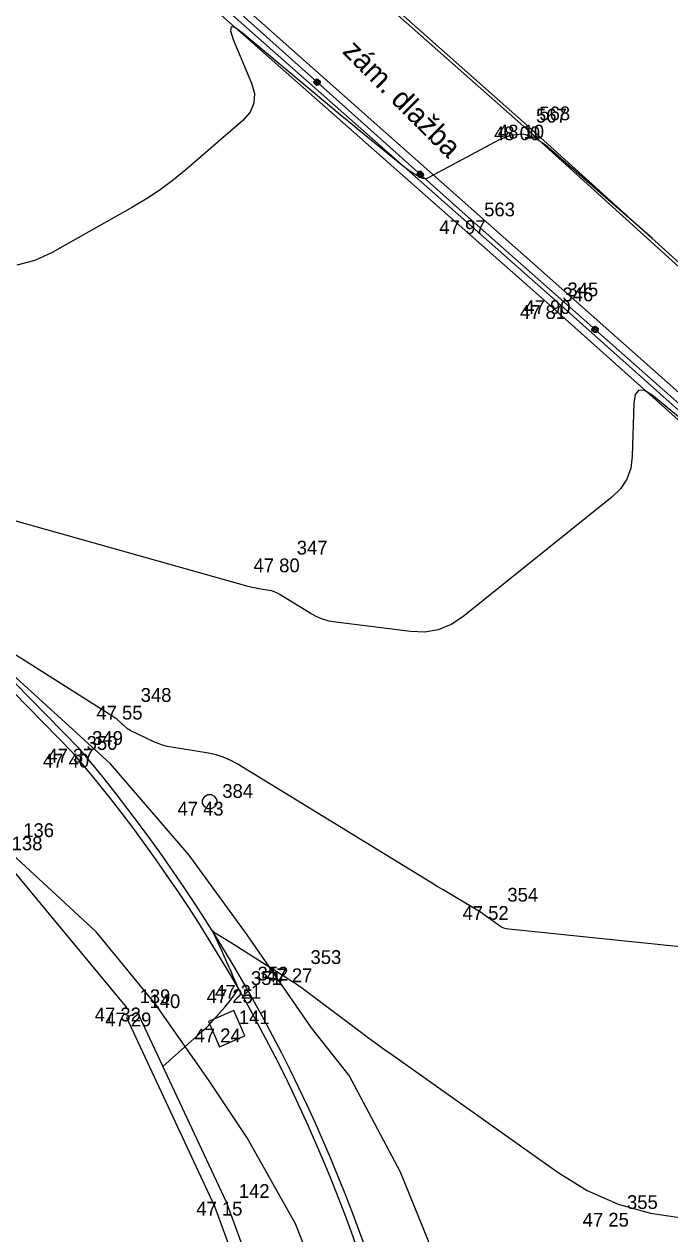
# Model space of a CAD drawing. Extents: x -702257 to -701487, y -1009871 to -1008841.
# Drawn here: x -701672.48 to -701660.77, y -1009023.63 to -1009001.71 of the extents above; entities that cross this region are included whole.
import ezdxf

# ---------------------------------------------------------------- set-up
doc = ezdxf.new("R2010")
doc.units = 0
for name, color, linetype in [('Ex_Major Contours', 7, 'Continuous'), ('Ex_Minor Contours', 7, 'Continuous'), ('Z_body', 7, 'Continuous'), ('Z_body_cisla', 7, 'Continuous'), ('Z_body_vysky_redukovane', 7, 'Continuous'), ('Z_katastr_hranice', 7, 'Continuous'), ('Z_komunikace', 7, 'Continuous'), ('Z_obruba', 7, 'Continuous'), ('Z_ploty', 7, 'Continuous'), ('Z_popisy', 7, 'Continuous'), ('Z_site_nerozlisene_znaky', 7, 'Continuous'), ('Z_site_vodovod_znaky', 7, 'Continuous'), ('Z_vstupy', 7, 'Continuous'), ('Z_zabradli', 7, 'Continuous'), ('Z_zabradli_znaky', 7, 'Continuous')]:
    doc.layers.add(name, color=color, linetype=linetype)

# ---------------------------------------------------------------- blocks, each defined once
blk = doc.blocks.new('POINT_DISPLAY')
blk.add_line((0, 0), (0, 0))
blk = doc.blocks.new('Z614')
for p, q in [((-0.13, 0.03), (-0.1, 0.08)), ((-0.13, -0.03), (-0.13, 0.03)), ((-0.1, 0.08), (-0.08, 0.1)), ((-0.08, 0.1), (-0.03, 0.13)), ((-0.03, 0.13), (0.03, 0.13)), ((0.03, 0.13), (0.08, 0.1)), ((0.08, 0.1), (0.1, 0.08)), ((0.1, 0.08), (0.13, 0.03)), ((0.13, 0.03), (0.13, -0.03)), ((-0.1, -0.08), (-0.13, -0.03)), ((-0.08, -0.1), (-0.1, -0.08)), ((-0.03, -0.13), (-0.08, -0.1)), ((0.03, -0.13), (-0.03, -0.13)), ((0.08, -0.1), (0.03, -0.13)), ((0.1, -0.08), (0.08, -0.1)), ((0.13, -0.03), (0.1, -0.08))]:
    blk.add_line(p, q)
blk = doc.blocks.new('Z608')
for p, q in [((0.25, 0.25), (-0.25, 0.25)), ((-0.25, 0.25), (-0.25, -0.25)), ((0.25, -0.25), (0.25, 0.25)), ((-0.25, -0.25), (0.25, -0.25))]:
    blk.add_line(p, q)
blk = doc.blocks.new('Z530')
for p, q in [((-0.05, 0.03), (-0.03, 0.05)), ((-0.05, -0.03), (-0.05, 0.03)), ((-0.03, 0.05), (0.03, 0.05)), ((-0.03, -0.03), (-0.03, 0.03)), ((-0.03, 0.03), (0.03, 0.03)), ((-0.03, -0.03), (0.03, 0.03)), ((0.03, 0.05), (0.05, 0.03)), ((0.03, 0.03), (0.03, -0.03)), ((0.05, 0.03), (0.05, -0.03)), ((-0.03, -0.05), (-0.05, -0.03)), ((0.03, -0.03), (-0.03, -0.03)), ((0.03, -0.05), (-0.03, -0.05)), ((0.05, -0.03), (0.03, -0.05))]:
    blk.add_line(p, q)

msp = doc.modelspace()

# ---------------------------------------------------------------- linework, layer by layer
at = {"layer": 'Ex_Major Contours'}
msp.add_lwpolyline([(-701661.09, -1009005.595), (-701663.036, -1009003.896), (-701663.232, -1009003.764), (-701663.436, -1009003.704), (-701663.649, -1009003.717), (-701663.869, -1009003.802), (-701665.142, -1009004.489), (-701665.179, -1009004.504), (-701665.216, -1009004.508), (-701665.252, -1009004.503), (-701665.289, -1009004.487), (-701665.434, -1009004.405), (-701665.47, -1009004.383), (-701665.505, -1009004.361), (-701665.539, -1009004.336), (-701665.572, -1009004.311), (-701666.416, -1009003.626), (-701666.567, -1009003.503), (-701666.718, -1009003.379), (-701666.869, -1009003.254), (-701667.018, -1009003.129), (-701668.527, -1009001.866), (-701668.661, -1009001.77), (-701668.732, -1009001.758), (-701668.742, -1009001.83), (-701668.69, -1009001.986), (-701668.359, -1009002.776), (-701668.307, -1009002.966), (-701668.316, -1009003.142), (-701668.387, -1009003.304), (-701668.518, -1009003.451), (-701669.548, -1009004.342), (-701669.777, -1009004.531), (-701670.016, -1009004.708), (-701670.263, -1009004.872), (-701670.518, -1009005.025), (-701671.975, -1009005.847), (-701672.291, -1009005.991), (-701672.617, -1009006.074)], dxfattribs=at)
at = {"layer": 'Ex_Minor Contours'}
for points in [[(-701660.416, -1009008.989), (-701661.094, -1009008.434), (-701661.235, -1009008.345), (-701661.337, -1009008.341), (-701661.4, -1009008.421), (-701661.426, -1009008.585), (-701661.454, -1009009.539), (-701661.482, -1009009.756), (-701661.553, -1009009.952), (-701661.667, -1009010.126), (-701661.823, -1009010.279), (-701664.525, -1009012.447), (-701664.742, -1009012.59), (-701664.973, -1009012.683), (-701665.218, -1009012.725), (-701665.478, -1009012.717), (-701666.828, -1009012.547), (-701666.952, -1009012.525), (-701667.071, -1009012.49), (-701667.185, -1009012.443), (-701667.296, -1009012.383), (-701667.861, -1009012.036), (-701667.903, -1009012.013), (-701667.947, -1009011.995), (-701667.992, -1009011.98), (-701668.039, -1009011.97), (-701668.23, -1009011.939), (-701668.278, -1009011.931), (-701668.325, -1009011.921), (-701668.372, -1009011.91), (-701668.419, -1009011.898), (-701673.905, -1009010.36)], [(-701660.328, -1009018.454), (-701660.823, -1009018.405), (-701663.696, -1009018.111), (-701663.741, -1009018.104), (-701663.784, -1009018.091), (-701663.826, -1009018.072), (-701663.865, -1009018.048), (-701664.099, -1009017.882), (-701664.118, -1009017.868), (-701664.124, -1009017.864), (-701664.206, -1009017.802), (-701664.22, -1009017.792), (-701664.235, -1009017.781), (-701664.251, -1009017.771), (-701664.266, -1009017.762), (-701664.883, -1009017.398), (-701664.991, -1009017.334), (-701665.098, -1009017.269), (-701665.206, -1009017.204), (-701665.313, -1009017.139), (-701668.622, -1009015.113), (-701668.745, -1009015.046), (-701668.872, -1009014.991), (-701669.004, -1009014.949), (-701669.141, -1009014.921), (-701669.809, -1009014.812), (-701669.892, -1009014.796), (-701669.974, -1009014.773), (-701670.054, -1009014.745), (-701670.132, -1009014.711), (-701670.561, -1009014.506), (-701670.577, -1009014.498), (-701670.592, -1009014.488), (-701670.607, -1009014.477), (-701670.621, -1009014.466), (-701670.676, -1009014.417), (-701670.689, -1009014.405), (-701670.703, -1009014.393), (-701670.717, -1009014.381), (-701670.731, -1009014.369), (-701670.804, -1009014.306), (-701670.821, -1009014.292), (-701670.838, -1009014.278), (-701670.856, -1009014.265), (-701670.875, -1009014.253), (-701672.459, -1009013.253), (-701672.643, -1009013.135)], [(-701669.97, -1009020.6), (-701669.231, -1009019.939), (-701669.183, -1009019.895), (-701669.137, -1009019.849), (-701669.092, -1009019.802), (-701669.048, -1009019.754), (-701668.846, -1009019.523), (-701668.819, -1009019.492), (-701668.793, -1009019.46), (-701668.767, -1009019.428), (-701668.742, -1009019.395), (-701668.595, -1009019.198), (-701668.593, -1009019.198), (-701668.59, -1009019.199), (-701668.702, -1009018.941), (-701668.717, -1009018.907), (-701668.732, -1009018.872), (-701668.747, -1009018.838), (-701668.763, -1009018.803), (-701668.826, -1009018.665), (-701668.858, -1009018.597), (-701668.889, -1009018.528), (-701669.021, -1009018.24), (-701669.027, -1009018.227), (-701669.046, -1009018.188), (-701669.064, -1009018.153), (-701669.066, -1009018.147), (-701669.066, -1009018.144), (-701669.063, -1009018.144), (-701669.058, -1009018.148), (-701669.03, -1009018.169), (-701669.024, -1009018.174), (-701669.017, -1009018.179), (-701669.009, -1009018.184), (-701669.002, -1009018.188), (-701668.849, -1009018.279), (-701668.822, -1009018.296), (-701668.794, -1009018.313), (-701668.766, -1009018.33), (-701668.739, -1009018.347), (-701668.026, -1009018.798), (-701667.969, -1009018.834), (-701667.833, -1009018.92), (-701667.74, -1009018.979), (-701667.7, -1009019.005), (-701667.611, -1009019.062), (-701667.585, -1009019.078), (-701667.532, -1009019.112), (-701667.5, -1009019.133), (-701667.489, -1009019.141), (-701667.479, -1009019.148), (-701666.295, -1009020.039), (-701666.254, -1009020.069), (-701666.213, -1009020.099), (-701666.172, -1009020.129), (-701666.131, -1009020.158), (-701665.924, -1009020.305), (-701665.841, -1009020.363), (-701665.8, -1009020.393), (-701662.798, -1009022.521), (-701662.27, -1009022.846), (-701661.713, -1009023.091), (-701661.127, -1009023.257), (-701660.513, -1009023.344)]]:
    msp.add_lwpolyline(points, dxfattribs=at)
at = {"layer": 'Z_katastr_hranice'}
for p, q in [((-701670.92, -1009015.11), (-701702.76, -1008986.15)), ((-701670.25, -1008999.84), (-701645.42, -1009021.86)), ((-701669.49, -1009016.77), (-701670.92, -1009015.11)), ((-701671.18, -1009018.16), (-701672.7, -1009016.75)), ((-701668.44, -1009018.21), (-701669.49, -1009016.77)), ((-701670.1, -1009019.47), (-701671.18, -1009018.16)), ((-701667.27, -1009019.9), (-701668.44, -1009018.21)), ((-701669.14, -1009020.84), (-701670.1, -1009019.47)), ((-701666.59, -1009020.76), (-701667.27, -1009019.9)), ((-701668.44, -1009021.89), (-701669.14, -1009020.84)), ((-701665.66, -1009022.51), (-701666.59, -1009020.76)), ((-701667.56, -1009023.45), (-701668.44, -1009021.89)), ((-701664.96, -1009024.22), (-701665.66, -1009022.51)), ((-701666.91, -1009025.11), (-701667.56, -1009023.45))]:
    msp.add_line(p, q, dxfattribs=at)
at = {"layer": 'Z_komunikace'}
for p, q in [((-701670.41, -1009000.22), (-701662.95, -1009006.8)), ((-701662.95, -1009006.8), (-701657.06, -1009012.06)), ((-701671.48, -1009014.84), (-701677.89, -1009008.31))]:
    msp.add_line(p, q, dxfattribs=at)
msp.add_ellipse((-701693.509, -1009033.405), major_axis=(-25.273, 13.954), ratio=0.997582, start_param=3.959461, end_param=4.347163, dxfattribs=at)
at = {"layer": 'Z_obruba'}
for p, q in [((-701668.79, -1008998.73), (-701663.37, -1009003.53)), ((-701663.42, -1009003.56), (-701668.87, -1008998.75)), ((-701662.85, -1009006.71), (-701670.29, -1009000.14)), ((-701663.37, -1009003.53), (-701658.81, -1009007.66)), ((-701663.42, -1009003.56), (-701658.81, -1009007.74)), ((-701656.97, -1009011.96), (-701662.85, -1009006.71)), ((-701678.01, -1009008.39), (-701671.58, -1009014.93))]:
    msp.add_line(p, q, dxfattribs=at)
msp.add_ellipse((-701693.261, -1009033.212), major_axis=(-23.123, 16.594), ratio=0.996244, start_param=4.074433, end_param=4.465516, dxfattribs=at)
at = {"layer": 'Z_ploty'}
for p, q in [((-701670.43, -1009019.62), (-701670.63, -1009019.71)), ((-701670.63, -1009019.71), (-701669.03, -1009023.13)), ((-701670.43, -1009019.62), (-701668.82, -1009023.05)), ((-701668.82, -1009023.05), (-701667.87, -1009025.63)), ((-701669.03, -1009023.13), (-701668.09, -1009025.69))]:
    msp.add_line(p, q, dxfattribs=at)
at = {"layer": 'Z_vstupy'}
msp.add_line((-701670.62, -1009019.53), (-701672.93, -1009016.75), dxfattribs=at)
at = {"layer": 'Z_zabradli'}
for p, q in [((-701664.37, -1009005.26), (-701670.22, -1009000.03)), ((-701655.57, -1009013.04), (-701664.37, -1009005.26))]:
    msp.add_line(p, q, dxfattribs=at)

# ---------------------------------------------------------------- block references
at = {"layer": 'Z_body'}
for p in [(-701663.37, -1009003.53), (-701663.42, -1009003.56), (-701664.37, -1009005.26), (-701662.95, -1009006.8), (-701662.85, -1009006.71), (-701667.76, -1009011.39), (-701670.59, -1009014.06), (-701671.58, -1009014.93), (-701671.48, -1009014.84), (-701669.12, -1009015.8), (-701663.95, -1009017.69), (-701667.51, -1009018.82), (-701668.48, -1009019.12), (-701668.59, -1009019.2), (-701670.62, -1009019.53), (-701670.43, -1009019.62), (-701668.81, -1009019.91), (-701668.82, -1009023.05), (-701661.77, -1009023.25)]:
    msp.add_blockref('POINT_DISPLAY', p, dxfattribs=at)
at = {"layer": 'Z_site_nerozlisene_znaky', "rotation": 23.399999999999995}
msp.add_blockref('Z608', (-701668.81, -1009019.91), dxfattribs=at)
at = {"layer": 'Z_site_vodovod_znaky'}
msp.add_blockref('Z614', (-701669.12, -1009015.8), dxfattribs=at)
at = {"layer": 'Z_zabradli_znaky'}
for p, rotation in [((-701667.17, -1009002.76), -41.80000000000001), ((-701665.3, -1009004.43), -41.80000000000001), ((-701662.13, -1009007.24), -41.50000000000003)]:
    msp.add_blockref('Z530', p, dxfattribs=dict(at, rotation=rotation))

# ---------------------------------------------------------------- texts
at = {"layer": 'Z_body_cisla'}
for s, p in [('567', (-701663.2, -1009003.49)), ('568', (-701663.14, -1009003.45)), ('563', (-701664.14, -1009005.19)), ('345', (-701662.63, -1009006.64)), ('346', (-701662.72, -1009006.73)), ('347', (-701667.54, -1009011.32)), ('348', (-701670.37, -1009013.99)), ('349', (-701671.25, -1009014.77)), ('350', (-701671.35, -1009014.86)), ('384', (-701668.89, -1009015.73)), ('136', (-701672.5, -1009016.44)), ('138', (-701672.71, -1009016.68)), ('354', (-701663.72, -1009017.61)), ('353', (-701667.29, -1009018.74)), ('351', (-701668.37, -1009019.12)), ('352', (-701668.25, -1009019.04)), ('139', (-701670.39, -1009019.45)), ('140', (-701670.21, -1009019.54)), ('141', (-701668.59, -1009019.83)), ('142', (-701668.59, -1009022.98)), ('355', (-701661.55, -1009023.18))]:
    msp.add_text(s, height=0.25, dxfattribs=at).set_placement(p)
at = {"layer": 'Z_body_vysky_redukovane'}
for s, p in [('48 00', (-701663.962, -1009003.81)), ('48 10', (-701663.891, -1009003.78)), ('47 97', (-701664.953, -1009005.51)), ('47 81', (-701663.492, -1009007.05)), ('47 90', (-701663.412, -1009006.96)), ('47 80', (-701668.323, -1009011.64)), ('47 55', (-701671.173, -1009014.31)), ('47 40', (-701672.143, -1009015.18)), ('47 37', (-701672.063, -1009015.09)), ('47 43', (-701669.703, -1009016.05)), ('47 52', (-701664.533, -1009017.94)), ('47 27', (-701668.093, -1009019.07)), ('47 21', (-701669.022, -1009019.37)), ('47 25', (-701669.173, -1009019.45)), ('47 32', (-701671.203, -1009019.78)), ('47 29', (-701671.013, -1009019.87)), ('47 24', (-701669.393, -1009020.16)), ('47 15', (-701669.362, -1009023.3)), ('47 25', (-701662.353, -1009023.5))]:
    msp.add_text(s, height=0.25, dxfattribs=at).set_placement(p)
at = {"layer": 'Z_popisy'}
msp.add_text('zám. dlažba', height=0.38, rotation=315, dxfattribs=at).set_placement((-701666.729, -1009002.218))

doc.saveas('drawing.dxf')
